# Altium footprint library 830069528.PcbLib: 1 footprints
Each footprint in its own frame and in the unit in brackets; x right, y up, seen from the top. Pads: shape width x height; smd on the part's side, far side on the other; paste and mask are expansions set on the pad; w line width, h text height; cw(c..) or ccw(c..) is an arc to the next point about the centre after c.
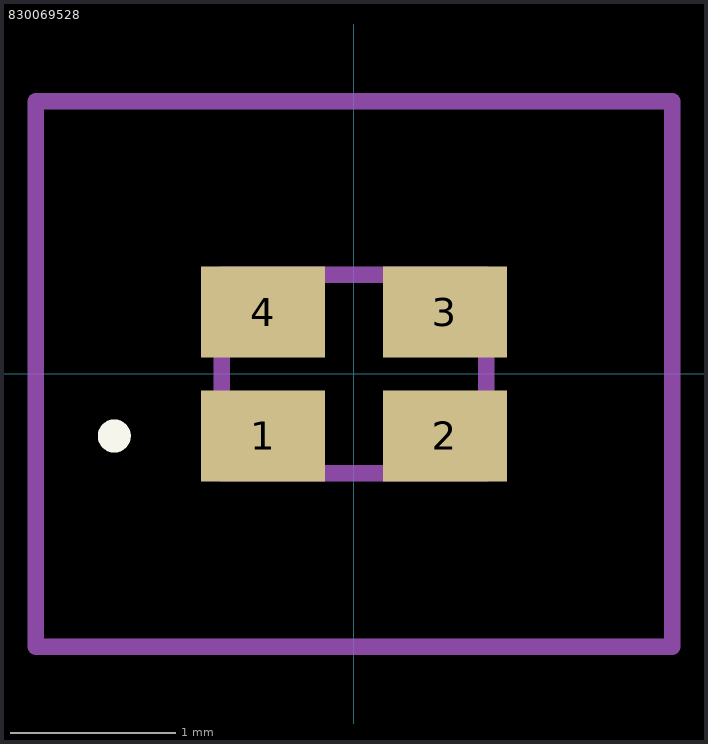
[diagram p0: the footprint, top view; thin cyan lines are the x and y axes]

## 830069528 [mm]
pads (4):
  rect 0.75x0.55 smd: 1(-0.55,-0.375) 2(0.55,-0.375) 3(0.55,0.375) 4(-0.55,0.375)
Top Overlay:
  lines w0.1: -1.5,-0.375 cw(c-1.45,-0.375) -1.4,-0.375 ; -1.5,-0.375 -1.5,-0.375 ; -1.5,-0.375 ccw(c-1.45,-0.375) -1.4,-0.375 ; -1.4,-0.375 -1.4,-0.375
Mechanical 15:
  lines w0.1: -0.8,-0.6 0.8,-0.6 0.8,0.6 -0.8,0.6 -0.8,-0.6
Mechanical 20:
  lines w0.1: -1.925,-1.65 1.925,-1.65 1.925,1.65 -1.925,1.65 -1.925,-1.65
